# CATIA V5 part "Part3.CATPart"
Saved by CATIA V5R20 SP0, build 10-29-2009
Part number: Part3
Bounding box of the stored display mesh (mm): x -50 to 50, y -100 to 100, z 0 to 5
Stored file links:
  C:\Users\Lenovo\Desktop\存钱\Part3.CATPart
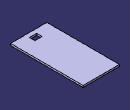
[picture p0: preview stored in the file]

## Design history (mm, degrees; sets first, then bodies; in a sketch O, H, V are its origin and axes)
Body1 (main body)
  Sketch1 on xy-plane, origin (0, 0, 0), H (1, 0, 0), V (0, 1, 0)
    line L1 (50, 100) -> (50, -100)
    line L2 (50, -100) -> (-50, -100)
    line L3 (-50, -100) -> (-50, 100)
    line L4 (-50, 100) -> (50, 100)
    length L4 = 100
    length L1 = 200
    vertical: L1 V, L3 V
    horizontal: L2 H, L4 H
    equidistance: L1 L3 O, L2 L4 O
  Pad1: profile Sketch1, direction (0, 0, 1), length 5
  Sketch2 on end face of Pad1, origin (0, 0, 5), H (1, 0, 0), V (0, 1, 0)
    point P1 (0, -80.6017)
    line L1 (10, -73.1017) -> (10, -88.1017)
    line L2 (10, -88.1017) -> (-10, -88.1017)
    line L3 (-10, -88.1017) -> (-10, -73.1017)
    line L4 (-10, -73.1017) -> (10, -73.1017)
    length L4 = 20
    length L1 = 15
    coincidence: P1 V
    vertical: L1 V, L3 V
    horizontal: L2 H, L4 H
    equidistance: L1 L3 P1, L2 L4 P1
  Pocket1: profile Sketch2, direction (0, 0, -1), length 5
